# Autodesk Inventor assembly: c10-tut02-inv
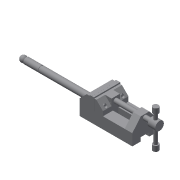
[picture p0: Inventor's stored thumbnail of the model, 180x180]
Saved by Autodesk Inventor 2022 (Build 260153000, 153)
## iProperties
Created: 2009-05
Part Number: c10-tut02-inv
Document SubType Name: Assembly
Designer: Sham
Author: Sham
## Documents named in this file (9)
- D:\PROJECTS_2021\Resources\Tutorial Files\c10_Inv_2022_tut\c10_tut02_inv\Drill Press Vice\Drill Press Vice Assembly.iam
- D:\PROJECTS_2021\Resources\Tutorial Files\c10_Inv_2022_tut\c10_tut02_inv\Drill Press Vice\Base.ipt
- D:\PROJECTS_2021\Resources\Tutorial Files\c10_Inv_2022_tut\c10_tut02_inv\Drill Press Vice\Safety Handle.ipt
- D:\PROJECTS_2021\Resources\Tutorial Files\c10_Inv_2022_tut\c10_tut02_inv\Drill Press Vice\Jaw Face.ipt
- D:\PROJECTS_2021\Resources\Tutorial Files\c10_Inv_2022_tut\c10_tut02_inv\Drill Press Vice\Movable Jaw.ipt
- D:\PROJECTS_2021\Resources\Tutorial Files\c10_Inv_2022_tut\c10_tut02_inv\Drill Press Vice\Cap Screw.ipt
- D:\PROJECTS_2021\Resources\Tutorial Files\c10_Inv_2022_tut\c10_tut02_inv\Drill Press Vice\Clamp Screw Handle.ipt
- D:\PROJECTS_2021\Resources\Tutorial Files\c10_Inv_2022_tut\c10_tut02_inv\Drill Press Vice\Clamp Screw.ipt
- D:\PROJECTS_2021\Resources\Tutorial Files\c10_Inv_2022_tut\c10_tut02_inv\Drill Press Vice\Handle Stop.ipt
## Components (11 placed, 8 different names)
1. Base:1 — Mate:1, Flush:1, Insert:1, Insert:2, Insert:3
2. Movable Jaw:1 — Mate:1, Flush:1, Insert:4, Insert:5, Insert:6, Insert:7, Insert:8
3. Safety Handle:1 — Insert:1
4. Jaw Face:1 — Insert:4, Insert:5, Mate:7
5. Jaw Face:2 — Insert:2, Insert:3, Mate:7
6. Cap Screw:1 — Insert:7
7. Cap Screw:2 — Insert:6
8. Clamp Screw:1 — Insert:8, Mate:2
9. Clamp Screw Handle:1 — Mate:2, Insert:9, Insert:10
10. Handle Stop:1 — Insert:10
11. Handle Stop:2 — Insert:9
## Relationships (14: Insert 10, Mate 3, Flush 1)
- Mate:1: Base:1 ↔ Movable Jaw:1
- Flush:1: Base:1 ↔ Movable Jaw:1
- Insert:1: Base:1 ↔ Safety Handle:1
- Insert:2: Base:1 ↔ Jaw Face:2
- Insert:3: Base:1 ↔ Jaw Face:2
- Insert:4: Movable Jaw:1 ↔ Jaw Face:1
- Insert:5: Movable Jaw:1 ↔ Jaw Face:1
- Insert:6: Movable Jaw:1 ↔ Cap Screw:2
- Insert:7: Movable Jaw:1 ↔ Cap Screw:1
- Insert:8: Movable Jaw:1 ↔ Clamp Screw:1
- Mate:2: Clamp Screw:1 ↔ Clamp Screw Handle:1
- Insert:9: Clamp Screw Handle:1 ↔ Handle Stop:2
- Insert:10: Clamp Screw Handle:1 ↔ Handle Stop:1
- Mate:7: Jaw Face:1 ↔ Jaw Face:2
